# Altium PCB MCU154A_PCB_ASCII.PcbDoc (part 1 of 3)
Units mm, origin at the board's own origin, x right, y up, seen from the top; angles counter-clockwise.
Board outline 105 x 85 mm, 2 copper layers (Top Layer, Bottom Layer), stack 1.6 mm thick; 186 components, 100 nets, 433 pads, 196 vias.
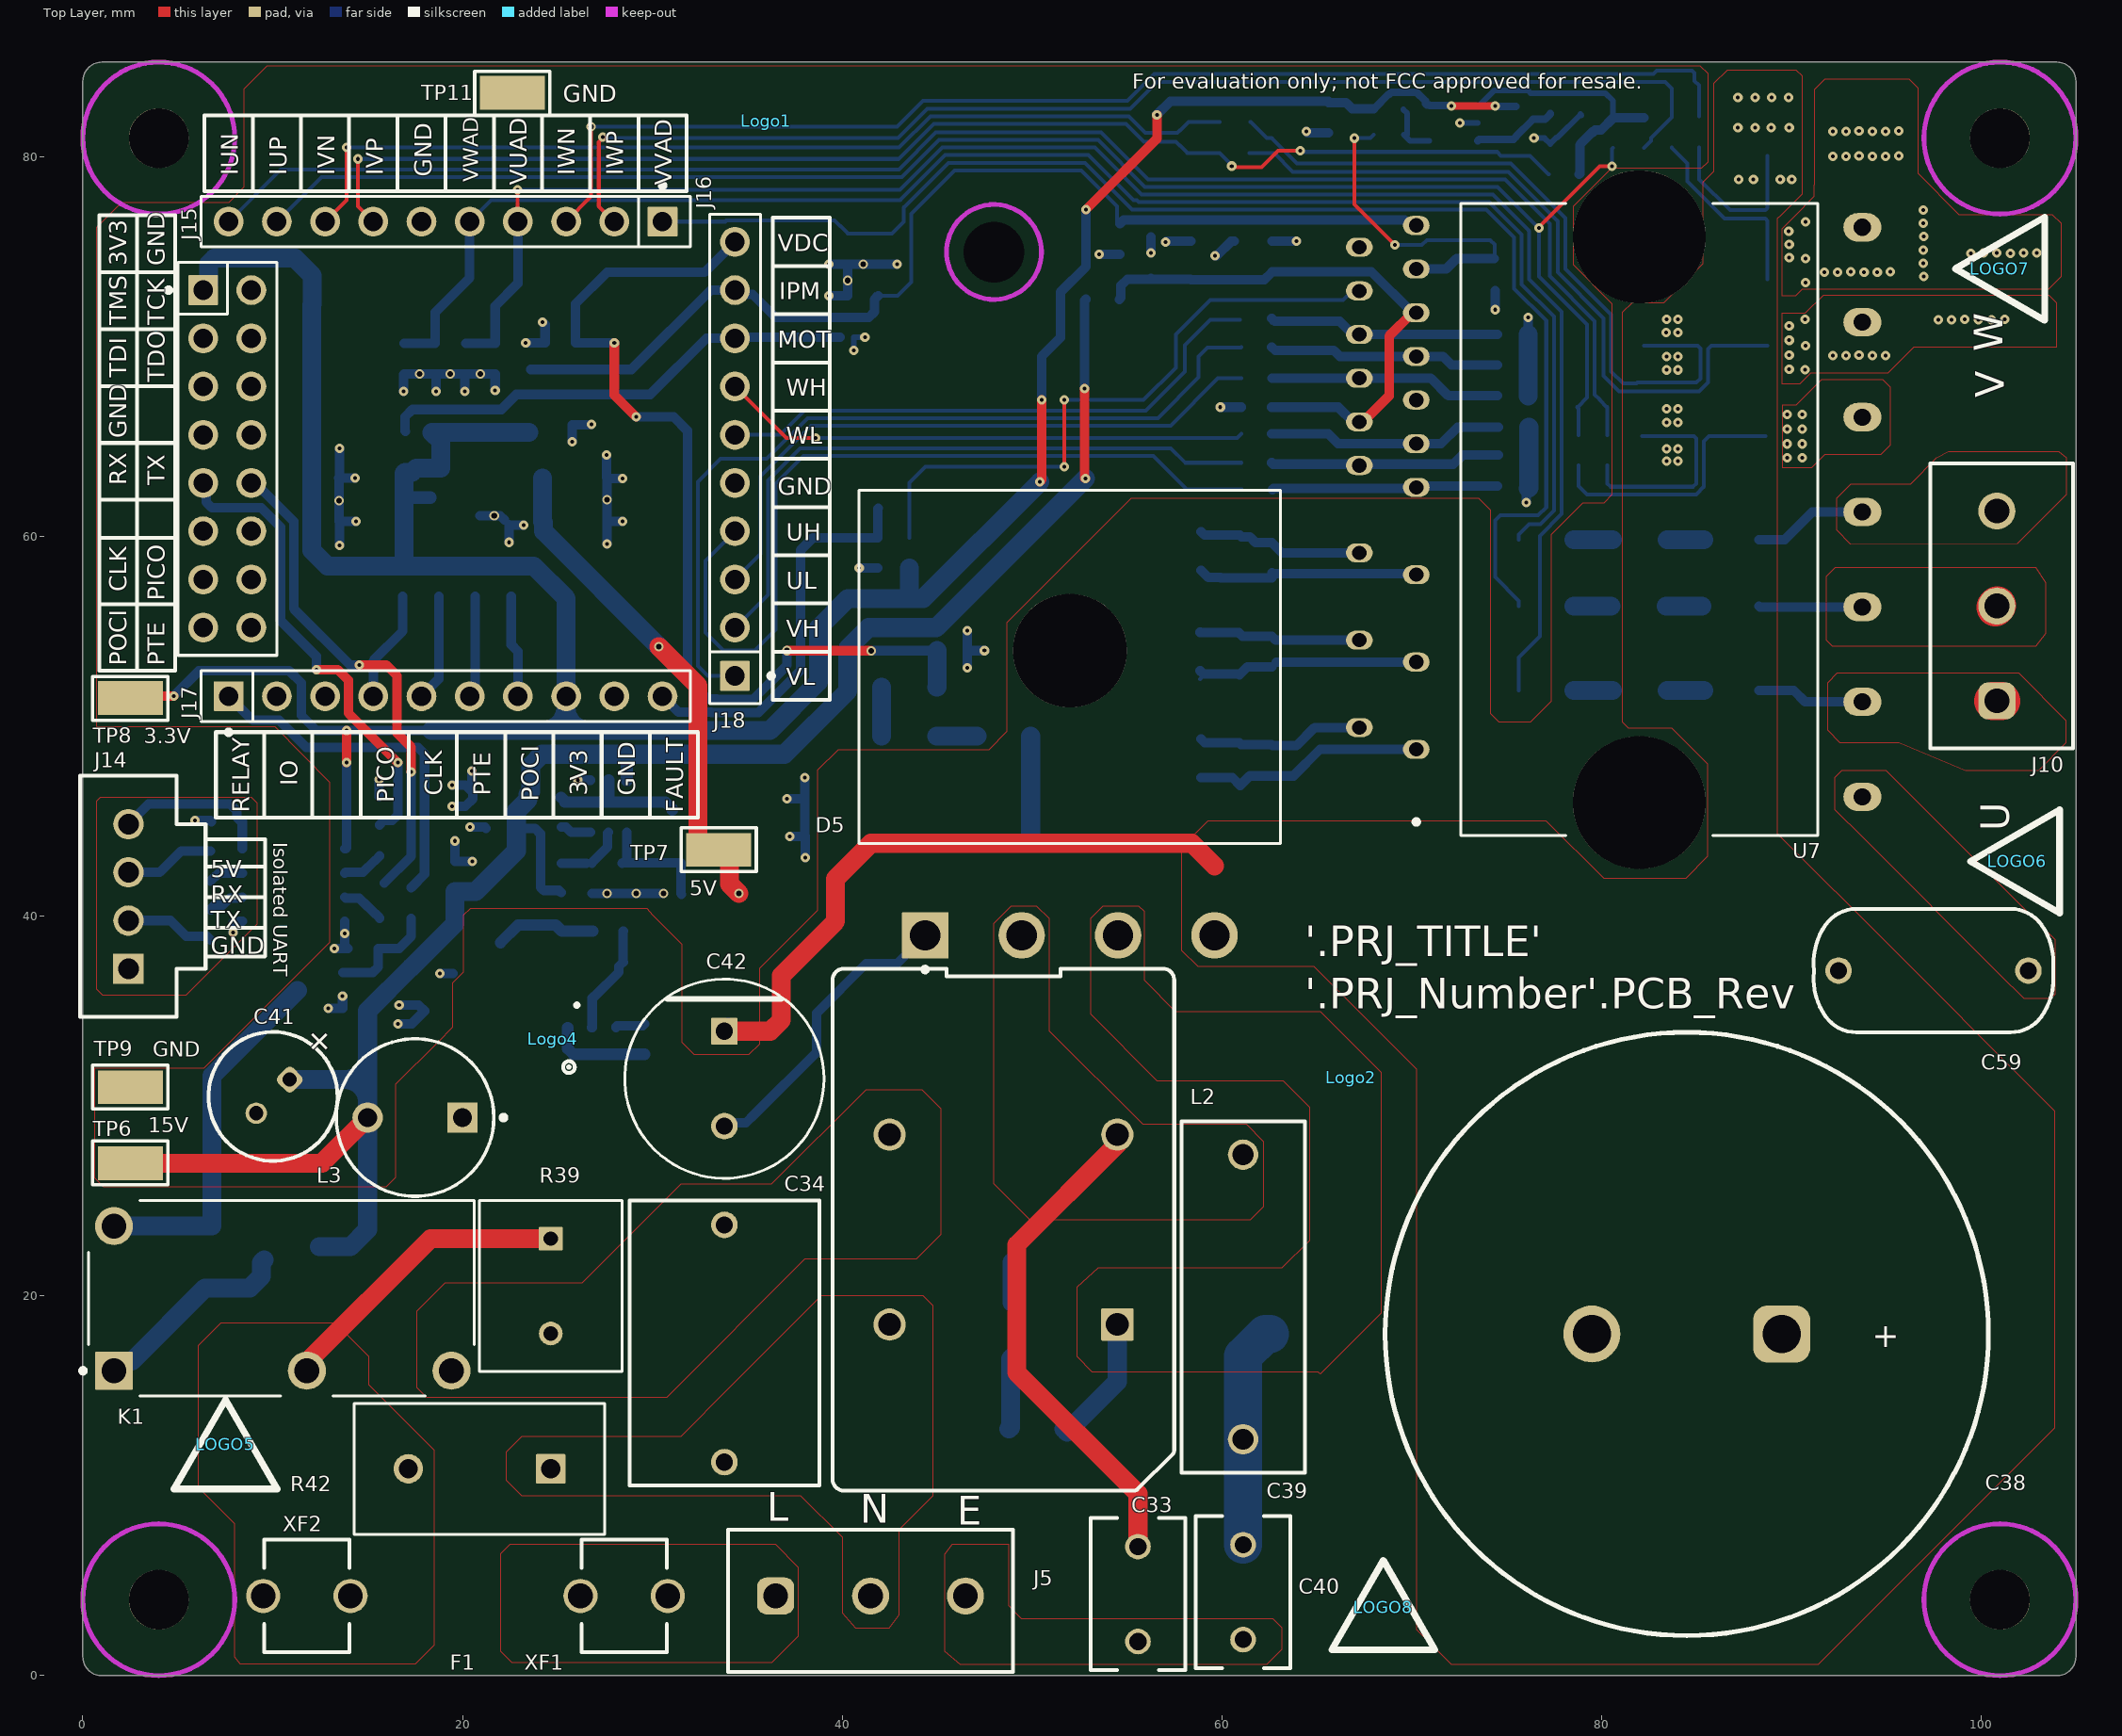
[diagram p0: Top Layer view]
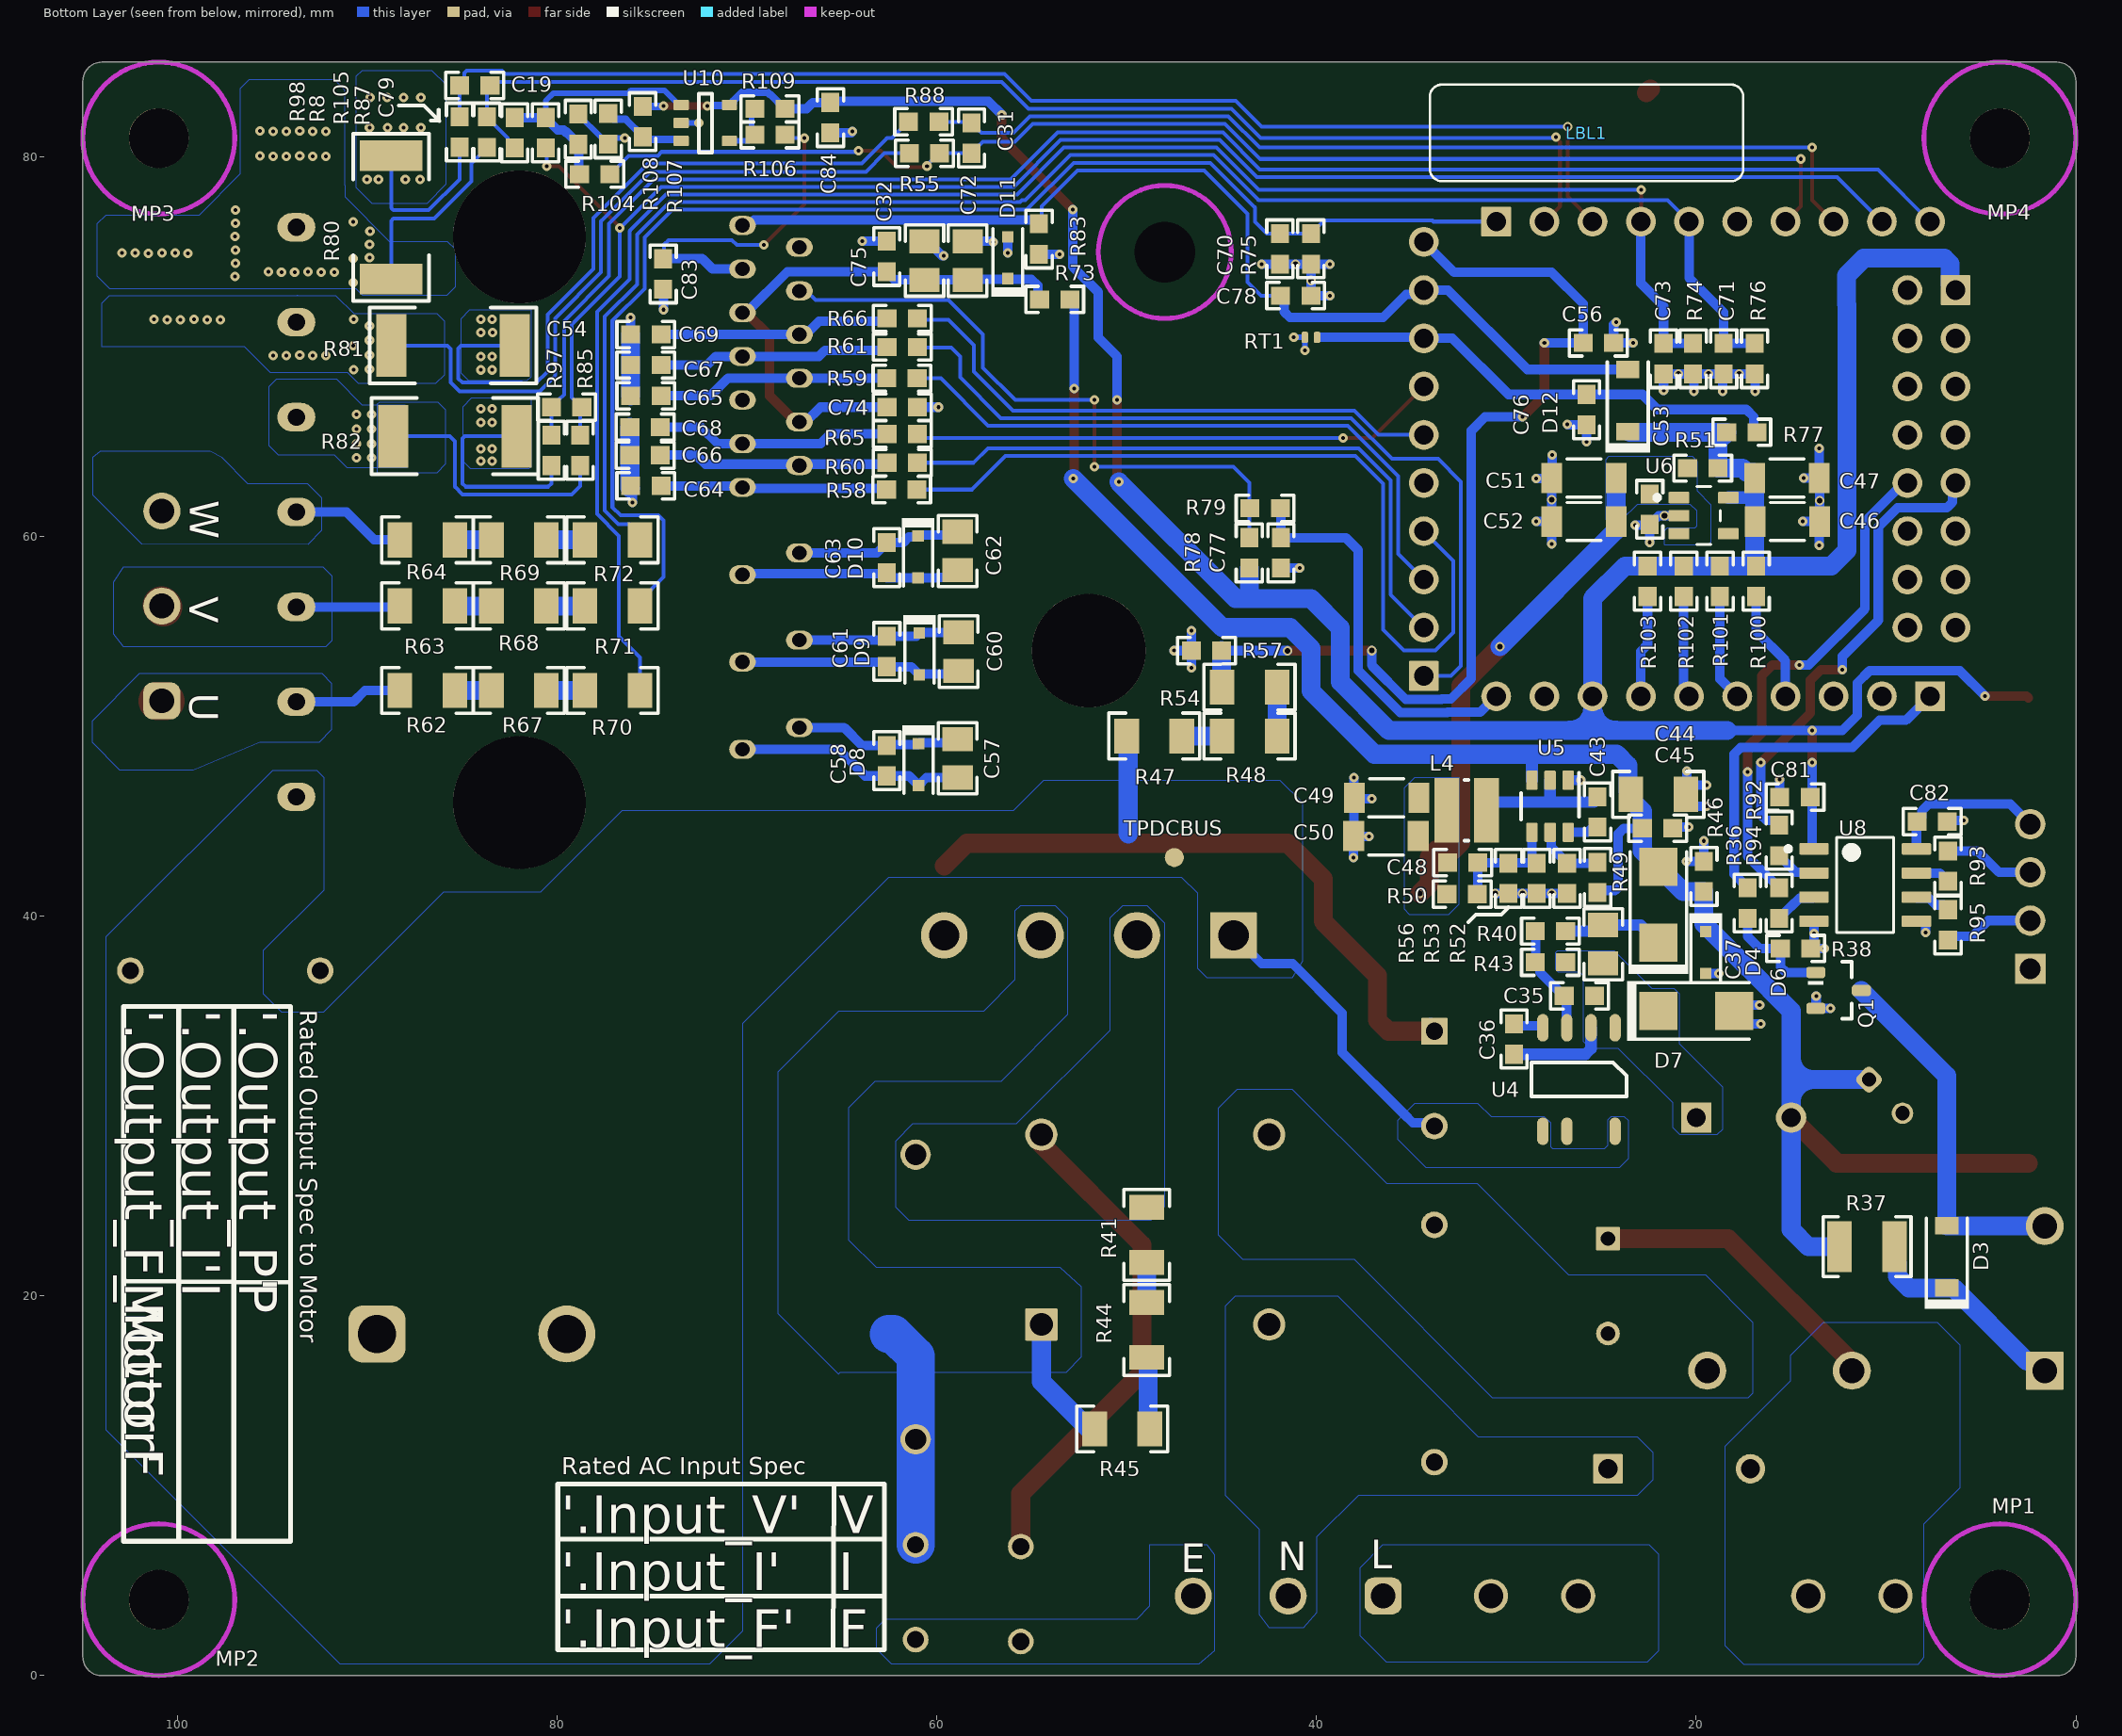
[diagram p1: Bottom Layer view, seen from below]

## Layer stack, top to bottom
Top Solder: solder mask 0.0102, Solder Resist, Dk 3.5
Top Layer: signal copper 0.07
Dielectric1: core 1.46, FR-4 High Tg, Dk 4.8
Bottom Layer: signal copper 0.07
Bottom Solder: solder mask 0.0102, Solder Resist, Dk 3.5

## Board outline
1,0 cw(c1,1) 0,1 0,84 cw(c1,84) 1,85 104,85 cw(c104,84) 105,84 105,1 cw(c104,1) 104,0

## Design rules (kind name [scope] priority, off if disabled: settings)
AcuteAngle [All] p0: scope1count=1 scope1_0_kind=Board scope1_0_value=Board scope2count=1 scope2_0_kind=Board scope2_0_value=Board commentlength=0 minimum=4.50000000000000E+0001
AcuteAngle [All] p1: minimum=4.50000000000000E+0001 checktracksonly=FALSE
AssemblyTestPointUsage [All] p0: scope1count=1 scope1_0_kind=Board scope1_0_value=Board scope2count=1 scope2_0_kind=Board scope2_0_value=Board commentlength=0
AssemblyTestPointUsage [All] p1: valid=2
AssemblyTestpoint [All] p0: scope1count=1 scope1_0_kind=Board scope1_0_value=Board scope2count=1 scope2_0_kind=Board scope2_0_value=Board commentlength=0
BoardOutlineClearance [All] p0 off: scope1count=1 scope1_0_kind=Board scope1_0_value=Board scope2count=1 scope2_0_kind=Board scope2_0_value=Board commentlength=172 gap=0 // Protel DXP Scope 1 Expression Was: OnCopper and Not InComponentClass('Logo') and not InComponentClass('FiducialMark') and not InRegion(1000,500,4000,800) and not InPoly
BoardOutlineClearance BoardOutlineClearance_Poly [All] p0 off: scope1count=1 scope1_0_kind=Board scope1_0_value=Board scope2count=1 scope2_0_kind=Board scope2_0_value=Board commentlength=58 gap=0 // Protel DXP Scope 1 Expression Was: OnCopper and IsPoly
BoardOutlineClearance BoardOutlineClearance_MountingHoles [All] p0 off: scope1count=1 scope1_0_kind=Board scope1_0_value=Board scope2count=1 scope2_0_kind=Board scope2_0_value=Board commentlength=86 gap=0 // Protel DXP Scope 1 Expression Was: OnCopper and InComponentClass('Mounting Holes')
BoardOutlineClearance BoardOutlineClearance_MountingHoles [OnCopper and InComponentClass('Mounting Holes')] p1: gap=0 ignorepadtopadclearanceinfootprint=FALSE
BoardOutlineClearance BoardOutlineClearance_Poly [OnCopper and IsPoly] p2: gap=0 ignorepadtopadclearanceinfootprint=FALSE
BoardOutlineClearance [OnCopper and Not InComponentClass('Logo') and not InComponentClass('FiducialMark') and not InRegion(1000,500,4000,800) and not InPoly] p3: gap=0 ignorepadtopadclearanceinfootprint=FALSE
Clearance [All] p0 off: scope1count=1 scope1_0_kind=Board scope1_0_value=Board scope2count=1 scope2_0_kind=Board scope2_0_value=Board commentlength=72 gap=0.2 // Protel DXP Scope 2 Expression Was: not HasFootprint('fiducial10-20')
Clearance SMTPadToTHHole [All] p0 off: scope1count=1 scope1_0_kind=Board scope1_0_value=Board scope2count=1 scope2_0_kind=Board scope2_0_value=Board commentlength=115 gap=0.15 // Protel DXP Scope 2 Expression Was: InSMTComponent and OnLayer('Bottom Layer') and not HasFootprint('TP_SM_1MM')
Clearance PB+ToPB- [All] p0: scope1count=1 scope1_0_kind=NetClass scope1_0_value=HV scope2count=1 scope2_0_kind=NetClass scope2_0_value=LV_Signal commentlength=0 gap=3
Clearance PB+ToACN [All] p0: scope1count=1 scope1_0_kind=NetClass scope1_0_value=V_BUS scope2count=1 scope2_0_kind=NetClass scope2_0_value=ACN commentlength=0 gap=1.5
Clearance PB+ToACL [All] p0: scope1count=1 scope1_0_kind=NetClass scope1_0_value=V_BUS scope2count=1 scope2_0_kind=NetClass scope2_0_value=ACL commentlength=0 gap=3
Clearance PB-ToACL [All] p0: scope1count=1 scope1_0_kind=NetClass scope1_0_value="LV Signal" scope2count=1 scope2_0_kind=NetClass scope2_0_value=ACL commentlength=0 gap=3
Clearance ISOToAll [All] p0 off: scope1count=1 scope1_0_kind=NetClass scope1_0_value=Isolation scope2count=1 scope2_0_kind=Board scope2_0_value=Board commentlength=105 gap=6 // Protel DXP Scope 2 Expression Was: not InNetClass('Isolation')   and (not  OnLayer('Keep-Out Layer'))
Clearance ACLToACN [All] p0: scope1count=1 scope1_0_kind=NetClass scope1_0_value=ACL scope2count=1 scope2_0_kind=NetClass scope2_0_value=ACN commentlength=0 gap=2
Clearance PB-ToACN [All] p0: scope1count=1 scope1_0_kind=NetClass scope1_0_value="LV Signal" scope2count=1 scope2_0_kind=NetClass scope2_0_value=ACN commentlength=0 gap=3
Clearance PB+ToPB- [InNetClass('HV') vs InNetClass('LV_Signal')] p1: gap=3 ignorepadtopadclearanceinfootprint=TRUE
Clearance PB-ToACN [InNetClass('LV Signal') vs InNetClass('ACN')] p2: gap=3 ignorepadtopadclearanceinfootprint=TRUE
Clearance ACLToACN [InNetClass('ACL') vs InNetClass('ACN')] p3: gap=2 ignorepadtopadclearanceinfootprint=FALSE
Clearance ISOToAll [InNetClass('Isolation') vs not InNetClass('Isolation')   and (not  OnLayer('Keep-Out Layer'))] p4: gap=6 ignorepadtopadclearanceinfootprint=TRUE
Clearance PB-ToACL [InNetClass('LV Signal') vs InNetClass('ACL')] p5: gap=3 ignorepadtopadclearanceinfootprint=TRUE
Clearance PB+ToACL [InNetClass('V_BUS') vs InNetClass('ACL')] p6: gap=3 ignorepadtopadclearanceinfootprint=TRUE
Clearance PB+ToACN [InNetClass('V_BUS') vs InNetClass('ACN')] p7: gap=1.5 ignorepadtopadclearanceinfootprint=TRUE
Clearance SMTPadToTHHole [not IsVia and OnLayer('Multi-Layer') and not InComponent('J1') and not InComponent('J2') and not InComponent('J3') and not InComponent('J4') and not InComponent('J12') and PadIsPlated vs InSMTComponent and OnLayer('Bottom Layer') and not HasFootprint('TP_SM_1MM')] p8: gap=0.15 ignorepadtopadclearanceinfootprint=FALSE except(3: SMDPad-THPad)
Clearance [All vs not HasFootprint('fiducial10-20')] p9: gap=0.2 ignorepadtopadclearanceinfootprint=TRUE
ComponentClearance [All] p0: scope1count=1 scope1_0_kind=Board scope1_0_value=Board scope2count=1 scope2_0_kind=Board scope2_0_value=Board commentlength=0 gap=0.508 collisioncheckmode=3
ComponentClearance ComponentClearance_THtoTH [All] p0 off: scope1count=1 scope1_0_kind=Board scope1_0_value=Board scope2count=1 scope2_0_kind=Board scope2_0_value=Board commentlength=54 gap=0.508 collisioncheckmode=3 // Protel DXP Scope 2 Expression Was: IsThruComponent
ComponentClearance ComponentClearance_THtoSMT [All] p0 off: scope1count=1 scope1_0_kind=Board scope1_0_value=Board scope2count=1 scope2_0_kind=Board scope2_0_value=Board commentlength=53 gap=0.762 collisioncheckmode=3 // Protel DXP Scope 2 Expression Was: IsSMTComponent
ComponentClearance ComponentClearance_SmallPassives [All] p0 off: scope1count=1 scope1_0_kind=Board scope1_0_value=Board scope2count=1 scope2_0_kind=Board scope2_0_value=Board commentlength=508 gap=0.38 collisioncheckmode=3 // Protel DXP Scope 2 Expression Was: HasFootprint('0201*') or HasFootprint('0402*') or HasFootprint('0508') or HasFootprint('0603*') or HasFootprint('0612') or HasFootprint('0805*') or HasFootprint('0815*') or HasFootprint('0830*') or HasFootprint('1206*') or HasFootprint('1210*') or HasFootprint('1808*') or HasFootprint('1812*') or HasFootprint('1825*') or HasFootprint('2010*') or HasFootprint('2220*') or HasFootprint('2225*') or HasFootprint('2512*') or HasFootprint('2728*') or HasFootprint('3518*')
ComponentClearance ComponentClearance_MountingHoles [All] p0: scope1count=1 scope1_0_kind=ComponentClass scope1_0_value="Mounting Holes" scope2count=1 scope2_0_kind=Board scope2_0_value=Board commentlength=0 gap=2.54 collisioncheckmode=3
ComponentClearance ComponentClearance_ScrewToNut [All] p0 off: scope1count=1 scope1_0_kind=Board scope1_0_value=Board scope2count=1 scope2_0_kind=Board scope2_0_value=Board commentlength=71 gap=0.127 collisioncheckmode=3 // Protel DXP Scope 2 Expression Was: (HasFootprint('Keystone_1902C'))
ComponentClearance ComponentClearance_Logo [All] p0: scope1count=1 scope1_0_kind=ComponentClass scope1_0_value=Logo scope2count=1 scope2_0_kind=Board scope2_0_value=Board commentlength=0 gap=0.762 collisioncheckmode=3
ComponentClearance ComponentClearance_Shunt [All] p0: scope1count=1 scope1_0_kind=ComponentClass scope1_0_value=Header scope2count=1 scope2_0_kind=ComponentClass scope2_0_value=Shunt commentlength=0 gap=0 collisioncheckmode=3
ComponentClearance ComponentClearance_MountingHoles_FiducialMarks [All] p0: scope1count=1 scope1_0_kind=ComponentClass scope1_0_value="Mounting Holes" scope2count=1 scope2_0_kind=ComponentClass scope2_0_value=FiducialMark commentlength=0 gap=1.27 collisioncheckmode=3
ComponentClearance ComponentClearance_MountingHoles_FiducialMarks [InComponentClass('Mounting Holes') vs InComponentClass('FiducialMark')] p1: gap=1.27 collisioncheckmode=3 verticalgap=0.254 showdistances=FALSE
ComponentClearance ComponentClearance_Shunt [InComponentClass('Header') vs InComponentClass('Shunt')] p2: gap=0 collisioncheckmode=3 verticalgap=0 showdistances=FALSE
ComponentClearance ComponentClearance_Logo [InComponentClass('Logo')] p3: gap=0.762 collisioncheckmode=3 verticalgap=0.254 showdistances=FALSE
ComponentClearance ComponentClearance_ScrewToNut [(HasFootprint('NY PMS 440 0025 PH')) vs (HasFootprint('Keystone_1902C'))] p4: gap=0.127 collisioncheckmode=3 verticalgap=0.254 showdistances=FALSE
ComponentClearance ComponentClearance_MountingHoles [InComponentClass('Mounting Holes')] p5: gap=2.54 collisioncheckmode=3 verticalgap=2540 showdistances=FALSE
ComponentClearance ComponentClearance_SmallPassives [HasFootprint('0201*') or HasFootprint('0402*') or HasFootprint('0508') or HasFootprint('0603*') or HasFootprint('0612') or HasFootprint('0805*') or HasFootprint('0815*') or HasFootprint('0830*') or HasFootprint('1206*') or HasFootprint('1210*') or HasFootprint('1808*') or HasFootprint('1812*') or HasFootprint('1825*') or HasFootprint('2010*') or HasFootprint('2220*') or HasFootprint('2225*') or HasFootprint('2512*') or HasFootprint('2728*') or HasFootprint('3518*') vs HasFootprint('0201*') or HasFootprint('0402*') or HasFootprint('0508') or HasFootprint('0603*') or HasFootprint('0612') or HasFootprint('0805*') or HasFootprint('0815*') or HasFootprint('0830*') or HasFootprint('1206*') or HasFootprint('1210*') or HasFootprint('1808*') or HasFootprint('1812*') or HasFootprint('1825*') or HasFootprint('2010*') or HasFootprint('2220*') or HasFootprint('2225*') or HasFootprint('2512*') or HasFootprint('2728*') or HasFootprint('3518*')] p6: gap=0.38 collisioncheckmode=3 verticalgap=0.254 showdistances=FALSE
ComponentClearance ComponentClearance_THtoSMT [IsThruComponent vs IsSMTComponent] p7: gap=0.762 collisioncheckmode=3 verticalgap=0.762 showdistances=FALSE
ComponentClearance ComponentClearance_THtoTH [IsThruComponent vs IsThruComponent] p8: gap=0.508 collisioncheckmode=3 verticalgap=0.762 showdistances=FALSE
ComponentClearance [All] p9: gap=0.508 collisioncheckmode=3 verticalgap=0.254 showdistances=FALSE
DiffPairsRouting [All] p0: scope1count=1 scope1_0_kind=Board scope1_0_value=Board scope2count=1 scope2_0_kind=Board scope2_0_value=Board commentlength=0
DiffPairsRouting [All] p1: maxlimit=2.54 minlimit=0.254 mostfreqgap=0.254 toplayer_minwidth=0.381 toplayer_maxwidth=0.381 toplayer_prefwidth=0.381 bottomlayer_minwidth=0.381 bottomlayer_maxwidth=0.381 bottomlayer_prefwidth=0.381 maxuncoupledlength=25.4
FabricationTestPointUsage TestPointUsage [All] p0: scope1count=1 scope1_0_kind=Board scope1_0_value=Board scope2count=1 scope2_0_kind=Board scope2_0_value=Board commentlength=0 valid=2 allowmultiple=FALSE
FabricationTestPointUsage TestPointUsage [All] p1: valid=2 allowmultiple=FALSE
FabricationTestpoint Testpoint [All] p0: scope1count=1 scope1_0_kind=Board scope1_0_value=Board scope2count=1 scope2_0_kind=Board scope2_0_value=Board commentlength=0 side=3 testpointundercomponent=TRUE minsize=1.016 maxsize=2.54 preferedsize=1.524 minholesize=0 maxholesize=1.016 preferedholesize=0.813 testpointgrid=0.025
FabricationTestpoint Testpoint [All] p1: side=3 testpointundercomponent=TRUE minsize=1.016 maxsize=2.54 preferedsize=1.524 minholesize=0 maxholesize=1.016 preferedholesize=0.813 testpointgrid=0.025 allowsidetop=TRUE allowsidebottom=TRUE usegrid=TRUE gridtolerance=0
FanoutControl Fanout_Small [All] p0 off: scope1count=1 scope1_0_kind=Board scope1_0_value=Board scope2count=1 scope2_0_kind=Board scope2_0_value=Board commentlength=84 // Protel DXP Scope 1 Expression Was: (CompPinCount < 5)   Fanout_Small (Default Rule)
FanoutControl Fanout_Default [All] p0: scope1count=1 scope1_0_kind=Board scope1_0_value=Board scope2count=1 scope2_0_kind=Board scope2_0_value=Board commentlength=30 // Fanout_Default (Default Rule)
FanoutControl Fanout_SOIC [All] p0 off: scope1count=1 scope1_0_kind=Board scope1_0_value=Board scope2count=1 scope2_0_kind=Board scope2_0_value=Board commentlength=71 // Protel DXP Scope 1 Expression Was: IsSOIC   Fanout_SOIC (Default Rule)
FanoutControl Fanout_BGA [All] p0 off: scope1count=1 scope1_0_kind=Board scope1_0_value=Board scope2count=1 scope2_0_kind=Board scope2_0_value=Board commentlength=69 // Protel DXP Scope 1 Expression Was: IsBGA   Fanout_BGA (Default Rule)
FanoutControl Fanout_LCC [All] p0 off: scope1count=1 scope1_0_kind=Board scope1_0_value=Board scope2count=1 scope2_0_kind=Board scope2_0_value=Board commentlength=69 // Protel DXP Scope 1 Expression Was: IsLCC   Fanout_LCC (Default Rule)
FanoutControl Fanout_LCC [IsLCC] p1: bgadir=Out bgaviamode=Centered fanoutstyle=Auto fanoutdirection=Alternating viagrid=0.025 // Fanout_LCC (Default Rule)
FanoutControl Fanout_BGA [IsBGA] p2: bgadir=Out bgaviamode=Centered fanoutstyle=Auto fanoutdirection=Alternating viagrid=0.025 // Fanout_BGA (Default Rule)
FanoutControl Fanout_Default [All] p4: bgadir=Out bgaviamode=Centered fanoutstyle=Auto fanoutdirection=Alternating viagrid=0.025 // Fanout_Default (Default Rule)
FanoutControl Fanout_Small [(CompPinCount < 5)] p5: bgadir=Out bgaviamode=Centered fanoutstyle=Auto fanoutdirection=OutThenIn viagrid=0.025 // Fanout_Small (Default Rule)
Height [All] p0: scope1count=1 scope1_0_kind=Board scope1_0_value=Board scope2count=1 scope2_0_kind=Board scope2_0_value=Board commentlength=0
HoleSize [All] p0: scope1count=1 scope1_0_kind=Board scope1_0_value=Board scope2count=1 scope2_0_kind=Board scope2_0_value=Board commentlength=0 absolutevalues=TRUE maxlimit=6.375 minlimit=0.2 maxpercent=80.000 minpercent=20.000
HoleSize [All] p1: absolutevalues=TRUE maxlimit=6.375 minlimit=0.2 maxpercent=80.000 minpercent=20.000
HoleToHoleClearance [All] p0: scope1count=1 scope1_0_kind=Board scope1_0_value=Board scope2count=1 scope2_0_kind=Board scope2_0_value=Board commentlength=0
LayerPairs [All] p0: scope1count=1 scope1_0_kind=Board scope1_0_value=Board scope2count=1 scope2_0_kind=Board scope2_0_value=Board commentlength=0 enforce=TRUE
MinimumAnnularRing [All] p0: scope1count=1 scope1_0_kind=Board scope1_0_value=Board scope2count=1 scope2_0_kind=Board scope2_0_value=Board commentlength=0 minimumring=0.2
MinimumAnnularRing MinimumAnnularRing_ThermalPadVias [All] p0 off: scope1count=1 scope1_0_kind=Board scope1_0_value=Board scope2count=1 scope2_0_kind=Board scope2_0_value=Board commentlength=63 minimumring=0.15 // Protel DXP Scope 1 Expression Was: IsVia and InAnyComponent
MinimumAnnularRing MinimumAnnularRing_ThermalPadVias [IsVia and InAnyComponent] p1: minimumring=0.15
MinimumAnnularRing [All] p2: minimumring=0.2
MinimumSolderMaskSliver [All] p0: scope1count=1 scope1_0_kind=Board scope1_0_value=Board scope2count=1 scope2_0_kind=Board scope2_0_value=Board commentlength=0
MinimumSolderMaskSliver MinimumSolderMaskSliver_Logo [All] p0: scope1count=1 scope1_0_kind=ComponentClass scope1_0_value=Logo scope2count=1 scope2_0_kind=ComponentClass scope2_0_value=Logo commentlength=0
MinimumSolderMaskSliver MinimumSolderMaskSliver_Logo [InComponentClass('Logo') vs InComponentClass('Logo')] p1: minsoldermaskwidth=0.018
MinimumSolderMaskSliver [All] p2: minsoldermaskwidth=0.1
NetAntennae [All] p0: scope1count=1 scope1_0_kind=Board scope1_0_value=Board scope2count=1 scope2_0_kind=Board scope2_0_value=Board commentlength=0
PasteMaskExpansion [All] p0: scope1count=1 scope1_0_kind=Board scope1_0_value=Board scope2count=1 scope2_0_kind=Board scope2_0_value=Board commentlength=0 expansion=0
PlaneClearance [All] p0: scope1count=1 scope1_0_kind=Board scope1_0_value=Board scope2count=1 scope2_0_kind=Board scope2_0_value=Board commentlength=0 clearance=0.508
PlaneConnect [All] p0: scope1count=1 scope1_0_kind=Board scope1_0_value=Board scope2count=1 scope2_0_kind=Board scope2_0_value=Board commentlength=0 planeconnectstyle=Direct reliefexpansion=0.254 reliefentries=4 reliefconductorwidth=0.254 reliefairgap=0.254
PlaneConnect [All] p1: planeconnectstyle=Direct reliefexpansion=0.254 reliefentries=4 reliefconductorwidth=0.254 reliefairgap=0.254
PolygonConnect "Thermal relief" [All] p0 off: scope1count=1 scope1_0_kind=Board scope1_0_value=Board scope2count=1 scope2_0_kind=Board scope2_0_value=Board commentlength=89 connectstyle=Relief reliefconductorwidth=0.5 reliefentries=4 polygonreliefangle="90 Angle" // Protel DXP Scope 2 Expression Was: InNet('GND') or innet('GND_ISO')  or innet('ubus')
PolygonConnect [All] p0: scope1count=1 scope1_0_kind=Board scope1_0_value=Board scope2count=1 scope2_0_kind=Board scope2_0_value=Board commentlength=0 connectstyle=Direct reliefconductorwidth=0.254 reliefentries=4 polygonreliefangle="90 Angle"
PolygonConnect "Thermal relief" [All vs InNet('GND') or innet('GND_ISO')  or innet('ubus')] p1: thpad.connectstyle=Relief thpad.reliefconductorwidth=0.5 thpad.reliefentries=4 thpad.polygonreliefangle="90 Angle" thpad.airgapwidth=0.254 smdpad.connectstyle=Direct smdpad.reliefconductorwidth=0.5 smdpad.reliefentries=4 smdpad.polygonreliefangle="90 Angle" smdpad.airgapwidth=0.254 via.connectstyle=Direct via.reliefconductorwidth=0.5 via.reliefentries=4 via.polygonreliefangle="90 Angle" via.airgapwidth=0.254
PolygonConnect [All] p2: connectstyle=Direct reliefconductorwidth=0.254 reliefentries=4 polygonreliefangle="90 Angle" airgapwidth=0.254
RoutingCorners [All] p0: scope1count=1 scope1_0_kind=Board scope1_0_value=Board scope2count=1 scope2_0_kind=Board scope2_0_value=Board commentlength=0 cornerstyle=45-Degree minsetback=2.54 maxsetback=2.54
RoutingLayers [All] p0: scope1count=1 scope1_0_kind=Board scope1_0_value=Board scope2count=1 scope2_0_kind=Board scope2_0_value=Board commentlength=0 top layer=Automatic bottom layer=Automatic
RoutingPriority [All] p0: scope1count=1 scope1_0_kind=Board scope1_0_value=Board scope2count=1 scope2_0_kind=Board scope2_0_value=Board commentlength=0
RoutingTopology [All] p0: scope1count=1 scope1_0_kind=Board scope1_0_value=Board scope2count=1 scope2_0_kind=Board scope2_0_value=Board commentlength=0 topology=Shortest
RoutingVias [All] p0: scope1count=1 scope1_0_kind=Board scope1_0_value=Board scope2count=1 scope2_0_kind=Board scope2_0_value=Board commentlength=0 holewidth=0.2 width=0.5 viastyle="Through Hole" minholewidth=0.2 minwidth=0.4 maxholewidth=1 maxwidth=1.4
RoutingVias ThermalPadVias [All] p0 off: scope1count=1 scope1_0_kind=Board scope1_0_value=Board scope2count=1 scope2_0_kind=Board scope2_0_value=Board commentlength=63 holewidth=0.2 width=0.5 viastyle="Through Hole" minholewidth=0.2 minwidth=0.5 maxholewidth=0.33 maxwidth=0.6 // Protel DXP Scope 1 Expression Was: IsVia and InAnyComponent
RoutingVias ThermalPadVias [IsVia and InAnyComponent] p1: holewidth=0.2 width=0.5 viastyle="Through Hole" minholewidth=0.2 minwidth=0.5 maxholewidth=0.33 maxwidth=0.6
RoutingVias [All] p2: holewidth=0.2 width=0.5 viastyle="Through Hole" minholewidth=0.2 minwidth=0.4 maxholewidth=1 maxwidth=1.4
ShortCircuit [All] p0: scope1count=1 scope1_0_kind=Board scope1_0_value=Board scope2count=1 scope2_0_kind=Board scope2_0_value=Board commentlength=0 allowed=FALSE
SilkToBoardRegionClearance [All] p0 off: scope1count=1 scope1_0_kind=Board scope1_0_value=Board scope2count=1 scope2_0_kind=Board scope2_0_value=Board commentlength=130 // Protel DXP Scope 1 Expression Was: Not ((IsComment or IsDesignator) And (Hide <> 'False')) and not InRegion(1000,500,4000,800)
SilkToBoardRegionClearance [Not ((IsComment or IsDesignator) And (Hide <> 'False')) and not InRegion(1000,500,4000,800)] p1:
SilkToSilkClearance [All] p0: scope1count=1 scope1_0_kind=Board scope1_0_value=Board scope2count=1 scope2_0_kind=Board scope2_0_value=Board commentlength=0
SilkToSilkClearance SilkToSilkClearance_Pb-FreeLogo [All] p0 off: scope1count=1 scope1_0_kind=Board scope1_0_value=Board scope2count=1 scope2_0_kind=Board scope2_0_value=Board commentlength=120 // Protel DXP Scope 2 Expression Was: (HasFootprint('Pb-Free_Overlay_Medium') OR HasFootprint('Pb-Free_Overlay_Small'))
SilkToSilkClearance SilkToSilkClearance_Pb-FreeLogo [(HasFootprint('Pb-Free_Overlay_Medium') OR HasFootprint('Pb-Free_Overlay_Small')) vs (HasFootprint('Pb-Free_Overlay_Medium') OR HasFootprint('Pb-Free_Overlay_Small'))] p1: silktosilkclearance=0
SilkToSilkClearance [All] p2: silktosilkclearance=0.1
SilkToSolderMaskClearance "Silk to Solder Mask Opening" [All] p0: scope1count=1 scope1_0_kind=Board scope1_0_value=Board scope2count=1 scope2_0_kind=Board scope2_0_value=Board commentlength=0
SilkToSolderMaskClearance SilkToComponentPadClearance [All] p0 off: scope1count=1 scope1_0_kind=Board scope1_0_value=Board scope2count=1 scope2_0_kind=Board scope2_0_value=Board commentlength=87 // Protel DXP Scope 1 Expression Was: (IsPad or IsFill or IsRegion) and InAnycomponent
SilkToSolderMaskClearance SilkToComponentPadClearance [(IsPad or IsFill or IsRegion) and InAnycomponent] p1: minsilkscreentomaskgap=0.127 clearancetoexposedcopper=TRUE
SilkToSolderMaskClearance "Silk to Solder Mask Opening" [All] p2: minsilkscreentomaskgap=0.1 clearancetoexposedcopper=FALSE
SolderMaskExpansion [All] p0: scope1count=1 scope1_0_kind=Board scope1_0_value=Board scope2count=1 scope2_0_kind=Board scope2_0_value=Board commentlength=0 expansion=0.05
SolderMaskExpansion [All] p1: expansion=0.05 istentingtop=FALSE
UnRoutedNet [All] p0: scope1count=1 scope1_0_kind=Board scope1_0_value=Board scope2count=1 scope2_0_kind=Board scope2_0_value=Board commentlength=0
UnRoutedNet [All] p1: checkbadconnections=TRUE
UnpouredPolygon [All] p0: scope1count=1 scope1_0_kind=Board scope1_0_value=Board scope2count=1 scope2_0_kind=Board scope2_0_value=Board commentlength=0
Width [All] p0: scope1count=1 scope1_0_kind=Board scope1_0_value=Board scope2count=1 scope2_0_kind=Board scope2_0_value=Board commentlength=0 maxlimit=5 minlimit=0.2 preferedwidth=0.3
Width [All] p1: maxlimit=5 minlimit=0.2 preferedwidth=0.3 minimp=50.000000 maximp=50.000000 favimp=50.000000 checkconnectedcopper=TRUE
14 further rules are at their usual default settings.

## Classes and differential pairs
component class MCU154A_Main: J5 J10
net class LV_Signal: 3.3V 5V 5V_ISO 15V GND GND_ISO IPM_15V IPM_CIN IPM_FAULT IPM_PWM_UH IPM_PWM_UL IPM_PWM_VH IPM_PWM_VL IPM_PWM_WH IPM_PWM_WL IPM_TEMP_AD IU_N IU_P IV_N IV_P IW_N IW_P MCU_TCK MCU_TDI MCU_TDO MCU_TMS MISC_IO MOTOR_TEMP_AD NetC43_1 NetC43_2 NetC48_2 NetC79_1 NetD3_1 NetD3_2 NetQ1_1 NetR8_1 NetR49_1 NetR55_1 NetR78_2 NetR82_2 NetR92_2 NetR93_1 NetR94_2 NetR95_1 NetR106_1 NetR107_1 NetU4_6 NetU6_4 NetU7_12 PWM_UH PWM_UL PWM_VH PWM_VL PWM_WH PWM_WL RELAY SPI_CLK(AI) SPI_CLK(DAC) SPI_PICO(AI) SPI_PICO(DAC) SPI_POCI(AI) SPI_POCI(DAC) SPI_PTE(AI) SPI_PTE(DAC) UART_RX UART_RX_ISO UART_TX UART_TX_ISO VDC_AD VU_AD VV_AD VW_AD
net class HV: Ubus
net class ACN: NetC39_2 NetR44_1 NEU
net class ACL: NetC33_1 NetC34_1 NetK1_2
component class Designator: C81 C82 J15 J16 J17 J18 R92 R93 R94 R95 R100 R101 R102 R103 U8
component class Logo: Logo2
component class Label: LBL1
component class Designator: C19 C31 C32 C54 C57 C58 C59 C60 C61 C62 C63 C64 C65 C66 C67 C68 C69 C70 C71 C72 C73 C74 C75 C76 C77 C78 C79 C83 C84 D8 D9 D10 D11 D12 R8 R55 R58 R59 R60 R61 R62 R63 R64 R65 R66 R67 R68 R69 R70 R71 R72 R73 R74 R75 R76 R77 R78 R79 R80 R81 R82 R83 R85 R87 R88 R97 R98 R104 R105 R106 R107 R108 R109 RT1 U7 U10

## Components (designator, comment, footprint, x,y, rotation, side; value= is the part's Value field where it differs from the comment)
C19 "GRM188R71E102KA01D" 0603 84.352,83.773 r180 bottom
C31 "GRM188R71E102KA01D" 0603 58.183,81 r270 bottom
C32 "GRM21BR6YA106KE43L" 0805_HV 60.662,74.548 r90 bottom
C33 "DE2E3KY222MA2BM01F" KY_800x500x1100 55.588,4.3 r270 top
C34 "890324024005" WCAP-FTX2_1500x1000x1600 33.8,17.5 r270 top
C35 "GRM1885C1H200JA01D" 0603 26.156,35.81 r180 bottom
C36 "GCM188R71H104KA57D" 0603 29.6,33.537 r270 bottom
C37 "GRM219R71H334KA88D" 0805_HV 24.907,38.531 r270 bottom
C38 "861141486026" WCAP-AI3H_3500x5700 84.5,18 r180 top
C39 "890324025017" WCAP-FTX2_1800x600x1200 61.126,19.95 r270 top
C40 "DE2E3KY222MA2BM01F" KY_800x500x1100 61.126,4.4 r90 top
C41 "35ZLJ100M6.3X11" Rubycon_630x1100 10.016,30.516 r225 top
C42 "860241375002" FP-860241375002_RADIAL-MFG 33.8,31.45 r270 top locked
C43 "GCM188R71H104KA57D" 0603 25.2,45.5 r90 bottom
C44 "GRM319R6YA106KA12D" 1206 22,46.426 r180 bottom
C45 "GCM188R71H104KA57D" 0603 22.038,44.641 r180 bottom
C46 "GRM31CR71E106KA12L" 1206_180 15.2,60.8 r180 bottom
C47 "GRM31CR71E106KA12L" 1206_180 15.224,63.089 r180 bottom
C48 "GRM1885C1H101JA01D" 0603 32.307,42.831 r180 bottom
C49 "GRM31CR71E106KA12L" 1206_180 36.349,44.23 r0 bottom
C50 "GRM31CR71E106KA12L" 1206_180 36.309,46.25 r0 bottom
C51 "GRM31CR71E106KA12L" 1206_180 25.921,63.089 r0 bottom
C52 "GRM31CR71E106KA12L" 1206_180 25.921,60.8 r0 bottom
C53 "GCM188R71H104KA57D" 0603 22.452,61.445 r270 bottom
C54 "GRM188R71E102KA01D" 0603 79.515,66.825 r180 bottom
C56 "GRM188R71H473KA61D" 0603 25.152,70.209 r180 bottom
C57 "GRM21BR6YA106KE43L" 0805_HV 58.913,48.326 r90 bottom
C58 "GCM188R71H104KA57D" 0603 62.644,48.2 r90 bottom
C59 "ECW-FD2W474Q1" ECWFD_1260x650x1270 97.5,37.142 r180 top
C60 "GRM21BR6YA106KE43L" 0805_HV 58.864,53.952 r90 bottom
C61 "GCM188R71H104KA57D" 0603 62.644,53.952 r90 bottom
C62 "GRM21BR6YA106KE43L" 0805_HV 58.913,59.249 r90 bottom
C63 "GCM188R71H104KA57D" 0603 62.646,58.9 r90 bottom
C64 "GRM188R71H221KA01D" 0603 75.34,62.679 r180 bottom
C65 "GRM188R71H221KA01D" 0603 75.34,67.424 r180 bottom
C66 "GRM188R71H221KA01D" 0603 75.378,64.297 r180 bottom
C67 "GRM188R71H221KA01D" 0603 75.34,69.04 r180 bottom
C68 "GRM188R71H221KA01D" 0603 75.378,65.772 r180 bottom
C69 "GRM188R71H221KA01D" 0603 75.34,70.65 r180 bottom
C70 "GRM188R71H473KA61D" 0603 41.933,75.163 r270 bottom
C71 "GRM188R71H473KA61D" 0603 18.559,69.378 r270 bottom
C72 "GRM21BR6YA106KE43L" 0805_HV 58.386,74.548 r90 bottom
C73 "GRM188R71H473KA61D" 0603 21.721,69.378 r270 bottom
C74 "GCM188R71H104KA57D" 0603 61.835,66.825 r180 bottom
C75 "GCM188R71H104KA57D" 0603 62.646,74.764 r90 bottom
C76 "GCM188R71H104KA57D" 0603 25.781,66.695 r270 bottom
C77 "GRM188R71E102KA01D" 0603 41.883,59.15 r270 bottom
C78 "GRM188R71E102KA01D" 0603 41.1,72.7 r0 bottom
C79 "GRM1885C1H101JA01D" 0603 78.897,81.466 r90 bottom
C81 "GRJ188R71E105KE11D" 0603 14.8,46.285 r180 bottom
C82 "GRJ188R71E105KE11D" 0603 7.567,44.994 r180 bottom
C83 "GRM188R71E102KA01D" 0603 74.43,73.844 r270 bottom
C84 "GCM188R71H104KA57D" 0603 65.619,82.08 r270 bottom
D3 "BAT54T1G" SOD-123 6.8,22.063 r90 bottom
D4 "US1M-13-F" SMA 22,40.614 r90 bottom
D5 "GBU15J" FP-GBU8J_Horizontal_Face_Down_SIP4-MFG 52,53.15 r0 top locked
D6 "MMSZ5248BS-7-F" SOD-323 19.5,38.1 r270 bottom
D7 "US1M-13-F" SMA 20,35.016 r180 bottom
D8 "MMSZ5248BS-7-F" SOD-323 60.974,48 r270 bottom
D9 "MMSZ5248BS-7-F" SOD-323 60.926,53.823 r270 bottom
D10 "MMSZ5248BS-7-F" SOD-323 60.999,58.935 r270 bottom
D11 "MMSZ5248BS-7-F" SOD-323 56.274,74.699 r90 bottom
D12 "BAT54T1G" SOD-123 23.61,67.171 r90 bottom
F1 "0215008.HXP" FP-0215008.HXP_FUSE_CARTRIDGE-MFG 20.146,4.2 r0 top
J5 "691137710003" 691137710003 41.5,3.95 r0 top
J10 "691137710003" 691137710003 101.09,56.351 r90 top
J14 "70543-0038" Molex_70543-0038 2.4,41.05 r90 top
J15 "TSW-108-07-T-D" FP-TSW-108-07-T-D_HDR16-MFG 7.61,64.1 r270 top
J16 "TSW-110-07-T-S" FP-TSW-110-07-T-S_HDR10-MFG 19.11,76.6 r180 top
J17 "TSW-110-07-T-S" FP-TSW-110-07-T-S_HDR10-MFG 19.11,51.6 r0 top
J18 "TSW-110-07-T-S" FP-TSW-110-07-T-S_HDR10-MFG 34.36,64.1 r90 top
K1 "G5Q-1A4-EU DC12" "FP-G5Q-1A4-EU DC12_PTH_RELAY_20MM0_10MM0-MFG" 10.46,19.875 r0 top
L2 "7448040707" WE-CMBNC_L 48.5,23.5 r180 top locked
L3 "768772182" WE-TI_8095 17.5,29.4 r180 top
L4 "78438335068" WE-MAIA_3015 32.1,45.595 r0 bottom
LBL1 "THT-14-423-10" Label_650x200 25.781,81.276 r180 bottom
Logo1 "CE Mark" CE_Mark_5mm 36,81.9 r0 top
Logo2 "Texas Instruments" TI_Symbol_Overlay_Small 66.8,31.518 r0 top
Logo3 "FCC disclaimer" FCC_disclaimer 47.377,95 r0 top
Logo4 "WEEE logo" WEEE_Minimum 24.74,33.543 r0 top
LOGO5 "CAUTION HOT SURFACE" IEC_HotSurface_Small 7.518,12.2 r0 top
LOGO6 "DANGER HIGH VOLTAGE" IEC_HighVoltage_Small 101.91,42.9 r90 top
LOGO7 "CAUTION HOT SURFACE" IEC_HotSurface_Small 101,74.115 r90 top
LOGO8 "DANGER HIGH VOLTAGE" IEC_HighVoltage_Small 68.511,3.6 r0 top
M46 "Comment" MARK 559.6,31.8 r0 top
M47 "Comment" Toolinghole 544.6,30.3 r0 top
M49 "Comment" MARK 554.6,31.8 r0 top
M50 "Comment" MARK 399.6,31.8 r0 top
M51 "Comment" MARK 399.602,138.799 r0 top
M52 "Comment" MARK 559.6,138.8 r0 top
M53 "Comment" Toolinghole 409.6,30.3 r0 top
M54 "Comment" Toolinghole 409.602,140.299 r0 top
M55 "Comment" Toolinghole 549.6,140.3 r0 top
M56 "Comment" Arrow 424.6,140.3 r0 top
M57 "Comment" Arrow 467.6,140.3 r180 bottom
M57 "Comment" "Bad Mark" 484.6,31.8 r0 top
M58 "Comment" "Bad Mark" 474.6,31.8 r0 top
M58 "Comment" "White oil-26X4" 524.6,28.3 r0 top
MP1 "970130365" FP-970130365_SPCAER_M3-MFG 4,4 r180 bottom locked
MP2 "970130365" FP-970130365_SPCAER_M3-MFG 101,4 r180 bottom locked
MP3 "970130365" FP-970130365_SPCAER_M3-MFG 101,81 r180 bottom
MP4 "970130365" FP-970130365_SPCAER_M3-MFG 4,81 r180 bottom
Q1 "2N7002P,215" SOT-23 12.5,36.1 r180 bottom
R8 "RC0603FR-0720RL" 0603 83.715,81.315 r90 bottom
R36 "RC0603FR-071KL" 0603 17.3,40.7 r270 bottom
R37 "RC1210FR-07180RL" 1210 11,22.6 r180 bottom
R38 "RC0603FR-0710KL" 0603 14.768,38.309 r0 bottom
R39 "B59770C0120A070" FP-B59770C0120A070_RADIAL-MFG 24.65,20.525 r270 top
R40 "RC0603FR-07133KL" 0603 27.68,39.222 r180 bottom
R41 "RC1206FR-07100KL" 1206 48.952,23.223 r90 bottom
R42 "IsoM3-275-B-L2" FP-IsoM3-275-B-L2_RADIAL-MFG 20.9,10.9 r180 top
R43 "RC0603FR-0710KL" 0603 27.68,37.583 r0 bottom
R44 "RC1206FR-07100KL" 1206 48.952,18.213 r90 bottom
R45 "RC1206FR-07100KL" 1206 50.239,13 r180 bottom
R46 "RC0603FR-0720KL" 0603 19.6,42.1 r270 bottom
R47 "RC1206FR-07332KL" 1206 48.555,49.5 r0 bottom
R48 "RC1206FR-07332KL" 1206 43.535,49.5 r0 bottom
R49 "RC0603FR-071M5L" 0603 25.2,42.052 r270 bottom
R50 "RC0603FR-07100KL" 0603 32.337,41.169 r0 bottom
R51 "RC0603JR-070RL" 0603 19.659,63.612 r180 bottom
R52 "RC0603FR-07133KL" 0603 26.811,42 r90 bottom
R53 "RC0603FR-0713K7L" 0603 28.401,42 r90 bottom
R54 "RC1206FR-07332KL" 1206 43.535,52.073 r180 bottom
R55 "RC0603FR-0720RL" 0603 60.662,80.2 r180 bottom
R56 "RC0603FR-0720KL" 0603 29.891,42 r90 bottom
R57 "RC0603FR-078K2L" 0603 45.8,54 r180 bottom
R58 "RC0603FR-07100RL" 0603 61.862,62.484 r0 bottom
R59 "RC0603FR-07100RL" 0603 61.844,68.349 r0 bottom
R60 "RC0603FR-07100RL" 0603 61.835,63.898 r0 bottom
R61 "RC0603FR-07100RL" 0603 61.835,69.992 r0 bottom
R62 "RC1206FR-07332KL" 1206 86.847,51.9 r0 bottom
R63 "RC1206FR-07332KL" 1206 86.847,56.351 r0 bottom
R64 "RC1206FR-07332KL" 1206 86.847,59.835 r0 bottom
R65 "RC0603FR-07100RL" 0603 61.835,65.414 r0 bottom
R66 "RC0603FR-07100RL" 0603 61.835,71.502 r0 bottom
R67 "RC1206FR-07332KL" 1206 82.029,51.9 r0 bottom
R68 "RC1206FR-07332KL" 1206 82.029,56.351 r0 bottom
R69 "RC1206FR-07332KL" 1206 82.029,59.835 r0 bottom
R70 "RC1206FR-07332KL" 1206 77.1,51.9 r0 bottom
R71 "RC1206FR-07332KL" 1206 77.1,56.351 r0 bottom
R72 "RC1206FR-07332KL" 1206 77.1,59.835 r0 bottom
R73 "RC0603JR-070RL" 0603 53.8,72.5 r0 bottom
R74 "RC0603FR-078K2L" 0603 20.166,69.378 r90 bottom
R75 "RC0603FR-078K2L" 0603 40.3,75.163 r90 bottom
R76 "RC0603FR-078K2L" 0603 16.923,69.378 r90 bottom
R77 "RC0603FR-071KL" 0603 17.6,65.5 r0 bottom
R78 "RC0603FR-0710KL" 0603 43.545,59.15 r90 bottom
R79 "RC0603FR-07100RL" 0603 42.714,61.496 r0 bottom
R80 "CSRN2512FT50L0" CSRN2512 88.754,76.823 r270 bottom
R81 "CSRN2512FT50L0" CSRN2512 85.5,70.068 r0 bottom
R82 "CSRN2512FT50L0" CSRN2512 85.397,65.297 r0 bottom
R83 "RC0603FR-075K1L" 0603 54.625,75.682 r90 bottom
R85 "RC0603FR-0720RL" 0603 78.807,64.55 r90 bottom
R87 "RC0603FR-075K1L" 0603 80.618,81.28 r90 bottom
R88 "RC0603FR-0720RL" 0603 60.702,81.859 r180 bottom
R92 "RC0603FR-07100RL" 0603 15.633,44 r270 bottom
R93 "RC0603FR-071KL" 0603 6.734,42.65 r90 bottom
R94 "RC0603FR-071KL" 0603 15.633,40.7 r270 bottom
R95 "RC0603FR-07100RL" 0603 6.738,39.55 r270 bottom
R97 "RC0603FR-0720RL" 0603 80.315,64.55 r90 bottom
R98 "RC0603FR-0720RL" 0603 85.152,81.318 r90 bottom
R100 "RC0603FR-0710KL" 0603 16.844,57.654 r270 bottom
R101 "RC0603FR-0710KL" 0603 18.751,57.654 r270 bottom
R102 "RC0603FR-0710KL" 0603 20.659,57.654 r270 bottom
R103 "RC0603FR-0710KL" 0603 22.566,57.654 r270 bottom
R104 "RC0603FR-075K1L" 0603 78.033,79.098 r0 bottom
R105 "RC0603FR-075K1L" 0603 82.25,81.28 r90 bottom
R106 "RC0603FR-07100RL" 0603 68.8,81.173 r180 bottom
R107 "RC0603FR-0720KL" 0603 75.505,81.864 r90 bottom
R108 "RC0603FR-071KL" 0603 77.32,81.487 r90 bottom
R109 "RC0603FR-0720KL" 0603 68.8,82.542 r0 bottom
RT1 "TMP6131DECR" DEC0002A 40.3,70.5 r180 bottom
TP6 "5015" Testpoint_Keystone_Miniature 2.5,27 r180 top
TP7 "5015" Testpoint_Keystone_Miniature 33.5,43.5 r180 top
TP8 "5015" Testpoint_Keystone_Miniature 2.5,51.5 r0 top
TP9 "5015" Testpoint_Keystone_Miniature 2.5,31 r180 top
TP11 "5015" Testpoint_Keystone_Miniature 22.626,83.382 r0 top
TPDCBUS "TP_SM_1MM" TP_SM_1MM 47.5,43.1 r0 bottom
U4 "UCC28881DR" D0007A_N 26.18,31.406 r270 bottom
U5 "TPS54202DDCR" DDC0006A_N 27.7,45.8 r270 bottom
U6 "TLV74033PDBVR" DBV0005A-MFG 19.609,61.11 r180 bottom
U7 "SLIMDIP-M" FP-SLIMDIP-S_SLIMDIP-MFG 82,60.9 r90 top locked
U8 "ISO6721BQDRQ1" D0008A-MFG 11.1,41.65 r180 bottom
U10 "LMV331QDBVRQ1" DBV0005A_L 72.204,81.798 r180 bottom
XF1 "01000056Z" Littelfuse_0100-0020_54_56 28.515,4.2 r0 top
XF2 "01000056Z" Littelfuse_0100-0020_54_56 11.8,4.2 r0 top

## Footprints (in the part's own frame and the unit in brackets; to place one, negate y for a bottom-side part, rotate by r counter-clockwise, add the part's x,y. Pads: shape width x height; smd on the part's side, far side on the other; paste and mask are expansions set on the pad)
0603 [mm] "0603 from SM-752 data"
  rect 1x0.95 smd: 1(-0.8,0) 2(0.8,0)
  silkscreen extent -1.52,-0.69 1.52,0.69
0805_HV [mil] "0805 with 30mil clearance between pads"
  rect 50x63 smd: 1(-40,0) 2(40,0)
  silkscreen extent -74,-40 74,40
1206 [mm] "1206 from SM-752 data"
  rect 1.3x1.85 smd: 1(-1.45,0) 2(1.45,0)
  silkscreen extent -2.4,-1.21 2.4,1.21
1206_180 [mm] "1206_180"
  rect 1.1x1.6 smd: 1(-1.7,0) 2(1.7,0)
  silkscreen extent -0.9,-1 0.9,1
1210 [mm] "1210 from SM-752 data"
  rect 1.3x2.7 smd: 1(-1.45,0) 2(1.45,0)
  silkscreen extent -2.32,-1.57 2.32,1.57
691137710003 [mm] "Horizontal Cable Entry with Pressure Clamp, pitch 5mm, 03p"
  rrect50% 1.95x1.95 hole 1.3: 1(-5,0.25)
  round 1.95 hole 1.3: 2(0,0.25) 3(5,0.25)
  silkscreen extent -7.5,-3.75 7.5,3.75
Arrow [mm] "·½Ïò¼ýÍ·"
"Bad Mark" [mm]
  round 2 on Bottom Solder: 2(0,0)
  round 2 on Top Solder: 2(0,0)
CE_Mark_5mm [mm] "Minimum text height for CE Mark"
CSRN2512 [mm] "STACKPOLE"
  rect 1.6x3.3 smd: 1(-3.25,0) 2(3.25,0)
  silkscreen extent -4.4,-2 4.4,2
D0007A_N [mm] "SOIC, 7-Leads, Body 4.9x3.9mm, Pitch 1.27mm, IPC Medium Density"
  oval 1.45x0.6 smd: 1(-2.725,1.905) 2(-2.725,0.635) 3(-2.725,-0.635) 4(-2.725,-1.905) 5(2.725,-1.905) 6(2.725,-0.635) 8(2.725,1.905)
  silkscreen extent -0.9,-2.5 0.9,2.5
D0008A-MFG [mm]
  rrect17% 1.55x0.6 smd paste+0: 1(-2.7,1.905) 2(-2.7,0.635) 3(-2.7,-0.635) 4(-2.7,-1.905) 5(2.7,-1.905) 6(2.7,-0.635) 7(2.7,0.635) 8(2.7,1.905)
  silkscreen extent -4.17,-2.5 1.5,2.5
DBV0005A-MFG [mm]
  rrect17% 1.1x0.6 smd paste+0 mask+0: 1(-1.3,0.95) 2(-1.3,0) 3(-1.3,-0.95) 4(1.3,-0.95) 5(1.3,0.95)
  silkscreen extent -2.58,-1.53 0.87,1.53
DBV0005A_L [mm] "SOT23, 5-Leads, Body 2.9x1.6mm, Pitch 0.95mm, Lead Span 2.8mm, IPC High Density"
  rrect18% 0.8x0.55 smd: 1(-1.275,0.95) 2(-1.275,0) 3(-1.275,-0.95) 4(1.275,-0.95) 5(1.275,0.95)
  silkscreen extent -0.35,-1.55 0.35,1.55
DDC0006A_N [mm]
  rrect17% 1x0.6 smd: 1(-1.375,0.95) 2(-1.375,0) 3(-1.375,-0.95) 4(1.375,-0.95) 5(1.375,0) 6(1.375,0.95)
  silkscreen extent -1.75,-1.52 0.7,1.53
DEC0002A [mm] "X1SON-2"
  rrect57% 0.35x0.6 smd mask+0: 1(-0.325,0) 2(0.325,0)
  rrect33% 0.3x0.5 on Bottom Paste: 1S(-0.35,0) 2S(0.35,0)
ECWFD_1260x650x1270 [mm] "TH, 2-Leads, Body 12.6x6.5mm"
  round 1.4 hole 0.9: 1(-5,0) 2(5,0)
  silkscreen extent -6.32,-3.25 6.32,3.25
FCC_disclaimer [mm]
FP-0215008.HXP_FUSE_CARTRIDGE-MFG [mm]
FP-970130365_SPCAER_M3-MFG [mm]
  round 3.15 hole 3.15 unplated paste-1000 mask+0: ""(0,0)
FP-860241375002_RADIAL-MFG [mm]
  rrect7% 1.4x1.4 hole 0.9 paste-1000 mask+0: 1(-2.5,0)
  round 1.4 hole 0.9 paste-1000 mask+0: 2(2.5,0)
  silkscreen extent -5.25,-5.25 5.25,5.25
FP-B59770C0120A070_RADIAL-MFG [mm]
  rrect8% 1.25x1.25 hole 0.75 paste-1000 mask+0: 1(-2.5,0)
  round 1.25 hole 0.75 paste-1000 mask+0: 2(2.5,0)
  silkscreen extent -4.5,-3.75 4.5,3.75
"FP-G5Q-1A4-EU DC12_PTH_RELAY_20MM0_10MM0-MFG" [mm]
  rrect5% 2x2 hole 1.3 paste-1000 mask+0: 1(-8.82,-3.81)
  round 2 hole 1.3 paste-1000 mask+0: 2(1.34,-3.81) 3(8.96,-3.81) 5(-8.82,3.81)
  silkscreen extent -10.57,-5.15 10.15,5.15
FP-GBU8J_Horizontal_Face_Down_SIP4-MFG [mm]
  rrect4% 2.45x2.45 hole 1.6 paste-1000 mask+0: 1(-7.62,-14.15)
  round 2.45 hole 1.6 paste-1000 mask+0: 2(-2.54,-14.15) 3(2.54,-14.15) 4(7.62,-14.15)
  round 6 hole 6 unplated paste-1000 mask+0: ""(0,0.85)
  silkscreen extent -11.1,-16.07 11.1,9.3
FP-IsoM3-275-B-L2_RADIAL-MFG [mm]
  rrect6% 1.55x1.55 hole 1 paste-1000 mask+0: 1(-3.75,0)
  round 1.55 hole 1 paste-1000 mask+0: 2(3.75,0)
  silkscreen extent -6.6,-3.45 6.6,3.45
FP-SLIMDIP-S_SLIMDIP-MFG [mm]
  rrect100% 1x1.4 hole 0.75 paste-1000 mask+0: 2(-12.1,11.75) 3(-10.95,14.75) 4(-7.5,11.75) 5(-6.35,14.75) 6(-2.9,11.75) 7(-1.75,14.75) 8(1.7,11.75) 9(2.85,14.75) 10(4,11.75) 11(5.15,14.75) 12(6.3,11.75) 13(7.45,14.75) 14(8.6,11.75) 15(9.75,14.75) 16(10.9,11.75) 17(12.05,14.75) 18(13.2,11.75) 19(14.35,14.75) 20(15.5,11.75)
  rrect100% 1.5x2 hole 0.9 paste-1000 mask+0: 21(15.4,-11.75) 22(10.4,-11.75) 23(5.4,-11.75) 24(0.4,-11.75) 25(-4.6,-11.75) 26(-9.6,-11.75) 27(-14.6,-11.75)
  round 7 hole 7 unplated paste-1000 mask+0: ""(-14.9,0) ""(14.9,0)
  silkscreen extent -16.65,-9.4 16.65,11.87
FP-TSW-108-07-T-D_HDR16-MFG [mm]
  rrect6% 1.57x1.57 hole 1.02 paste+0 mask+0: 1(-8.89,-1.27)
  round 1.57 hole 1.02 paste+0 mask+0: 2(-8.89,1.27) 3(-6.35,-1.27) 4(-6.35,1.27) 5(-3.81,-1.27) 6(-3.81,1.27) 7(-1.27,-1.27) 8(-1.27,1.27) 9(1.27,-1.27) 10(1.27,1.27) 11(3.81,-1.27) 12(3.81,1.27) 13(6.35,-1.27) 14(6.35,1.27) 15(8.89,-1.27) 16(8.89,1.27)
  silkscreen extent -10.35,-3.22 10.35,2.61
FP-TSW-110-07-T-S_HDR10-MFG [mm]
  rrect6% 1.57x1.57 hole 1.02 paste+0 mask+0: 1(-11.43,0)
  round 1.57 hole 1.02 paste+0 mask+0: 2(-8.89,0) 3(-6.35,0) 4(-3.81,0) 5(-1.27,0) 6(1.27,0) 7(3.81,0) 8(6.35,0) 9(8.89,0) 10(11.43,0)
  silkscreen extent -12.89,-2.02 12.89,1.34
IEC_HighVoltage_Small [mm]
  silkscreen extent -2.72,-2.24 2.72,2.47
IEC_HotSurface_Small [mm]
  silkscreen extent -2.72,-2.36 2.72,2.35
KY_800x500x1100 [mm] "TH, 2- Leads, Body 8x5mm, Pin Spacing 5mm"
  round 1.35 hole 0.9: 1(-2.5,0) 2(2.5,0)
  silkscreen extent -4,-2.5 4,2.5
Label_650x200 [mil] "Thermal Transfer Label"
  round 1 on Mech14: 0(0,0)
  silkscreen extent -325,-100 325,100
Littelfuse_0100-0020_54_56 [mm] "Littelfuse"
  round 1.8 hole 1.3: 1(-2.3,0) 2(2.3,0)
  silkscreen extent -2.25,-2.97 2.25,2.97
MARK [mm]
  round 1 smd mask+0: 1(0,0)
  round 1 smd far side mask+0: 2(0,0)
Molex_70543-0038 [mm] "Header(shrouded), 2.54mm, 4x1, TH"
  rect 1.6x1.6 hole 1.09: 1(-3.81,0)
  round 1.6 hole 1.09: 2(-1.27,0) 3(1.27,0) 4(3.81,0)
  silkscreen extent -6.35,-4.06 6.35,2.54
Rubycon_630x1100 [mm] "TH, 2-Leads, Dia 6.3mm, Lead Spacing 2.5mm"
  rrect50% 1.125x1.125 hole 0.75: 1(-1.25,0)
  round 1.125 hole 0.75: 2(1.25,0)
  silkscreen extent -3.4,-3.4 3.41,3.4
SMA [mm] "Molded Diode, 2-Leads, Body 4.3x2.6mm, IPC Medium Density, based on OnSemi component dimensions and land pattern"
  rect 2x2 smd: 1(-2,0) 2(2,0)
  silkscreen extent -3.66,-1.57 2.79,1.57
SOD-123 [mm] "On Semi recommended land pattern"
  rect 0.915x1.22 smd: 1(-1.637,0) 2(1.637,0)
  silkscreen extent -2.74,-1.17 2.03,1.17
SOD-323 [mm] "NXP recommended land pattern"
  rect 0.6x0.6 smd paste-0.05: 1(-1.1,0) 2(1.1,0)
  silkscreen extent -2.06,-0.86 1.53,0.86
SOT-23 [mm] "SOT23, 3-Leads, Body 2.9x1.3mm, Pitch 0.95mm, Lead Span 2.5mm, IPC Medium Density"
  rrect50% 1x0.6 smd: 1(-1.2,0.95) 2(-1.2,-0.95) 3(1.2,0)
  silkscreen extent -1.63,-1.5 0.7,1.5
Testpoint_Keystone_Miniature [mil] "Miniature SMT test point"
  rect 135x70 smd: 1(0,0)
  silkscreen extent -78,-46 78,45
TI_Symbol_Overlay_Small [mm]
Toolinghole [mm]
  round 2 hole 2 unplated: 1(0,0)
  silkscreen extent -1.41,-1.41 1.41,1.41
TP_SM_1MM [mm] "1mm Test Point, SMT"
  round 1 smd paste-0.5: 1(0,0)
WCAP-AI3H_3500x5700 [mm] "TH, 2-Leads, Dia 35mm"
  rrect50% 3x3 hole 2: 1(-5,0)
  round 3 hole 2: 2(5,0)
WCAP-FTX2_1500x1000x1600 [mm] "TH, 2-Leads, Body 15x10mm, Pin Spacing 12.5mm"
  round 1.4 hole 0.9: 1(-6.25,0) 2(6.25,0)
  silkscreen extent -7.52,-5 7.48,5
WCAP-FTX2_1800x600x1200 [mm] "TH, 2-Leads, Body 18x6mm, Lead Spacing 15mm"
  round 1.6 hole 1.1: 1(-7.5,0) 2(7.5,0)
  silkscreen extent -9.25,-3.25 9.25,3.25
WE-CMBNC_L [mm] "TH, 4-Leads, Body 19x28mm"
  rrect6% 1.7x1.7 hole 1.2: 1(-6,5)
  round 1.7 hole 1.2: 2(-6,-5) 3(6,-5) 4(6,5)
  silkscreen extent -9,-13.75 9,13.75
WE-MAIA_3015 [mm] "SMD, 2-Leads, Body 3x3mm"
  rect 1.3x3.4 smd: 1(-1.05,0) 2(1.05,0)
  silkscreen extent -0.1,-1.6 0.1,1.6
WE-TI_8095 [mm] "Wurth WE-TI 8095"
  rect 1.6x1.6 hole 1: 1(-2.5,0)
  round 1.6 hole 1: 2(2.5,0)
  silkscreen extent -4.79,-4.15 4.15,4.15
WEEE_Minimum [mm] "WEEElie bin"
  silkscreen extent 0.56,-1.79 1.38,1.88
"White oil-26X4" [mm] "¶þÎ¬Âë°×ÓÍ¿ò"
  silkscreen extent -26,0 0,4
